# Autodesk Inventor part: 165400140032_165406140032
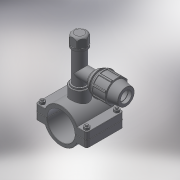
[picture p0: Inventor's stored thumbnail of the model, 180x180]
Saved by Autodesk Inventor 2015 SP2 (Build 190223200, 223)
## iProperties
Created: 2017-05
Part Number: 165400140032_165406140032
Material: Generic
Description: PLASSON TAPPER FOR PE+PVC PIPE 140-32
Document SubType Name: Modeling
Designer: KIM
Density: 1 g/cm^3
Appearance: Default
Author: KIM
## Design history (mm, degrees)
derived "16540.ipt"
feature "Solid1::16540.ipt"
feature "Solid2::16540.ipt"
tag "TaggingFeature1"
body "Solid1"
other parameters: "d0" = 154, "d1" = 201, "d4" = 136, "d5" = 0, "d6" = 10.05, "d7" = 201, "d8" = 0.1, "d10" = 0, "d11" = 1.4, "d14" = 50.6376, "d20" = 1.4, "d23" = 1.4, "d36" = 15, "d37" = 12, "d38" = 78, "d39" = 0, "d40" = 3, "d41" = 5, "d42" = 0, "d44" = 3, "d45" = 0, "d46" = 1.4, "d51" = 106, "d52" = 38.952, "d53" = 25, "d54" = 0, "d55" = 32, "d57" = 0, "d58" = 151.2, "d60" = 0, "d62" = 15, "d63" = 12, "d66" = 112, "d67" = 32, "d68" = 9.08333, "d69" = 21.8, "d70" = 64, "d71" = 48, "d72" = 1.55714, "d73" = 51.2, "d74" = 120 deg, "d75" = 48, "d76" = 10 deg, "d77" = 57.6, "d78" = 32.7, "d79" = 71, "d80" = 25.6, "d81" = 109, "d82" = 7.1, "d87" = 15.57143, "d90" = 59.52, "d91" = 35 deg, "d92" = 17.5 deg, "d94" = 0, "d96" = 360 deg, "d98" = 0.64, "d99" = 78.1, "d100" = 35.0568, "d101" = 135 deg, "d102" = 1.28, "d105" = 3.2, "d106" = 0, "d107" = 0.1, "d108" = 35.0568, "d109" = 42.8472, "d111" = 26.4, "d112" = 6.6, "d113" = 3.63333, "d116" = 0, "d117" = 38, "d118" = 21.8, "d119" = 0, "d121" = 132, "d122" = 59, "B_" = 32, "G_" = 38.952, "A_" = 106, "L_" = 201, "L_1" = 136, "l_2" = 25, "d_1" = 32, "E_" = 64, "l_" = 71, "H_" = 109, "H_1" = 59, "H_2" = 132
